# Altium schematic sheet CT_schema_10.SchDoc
size 209 x 185 mm
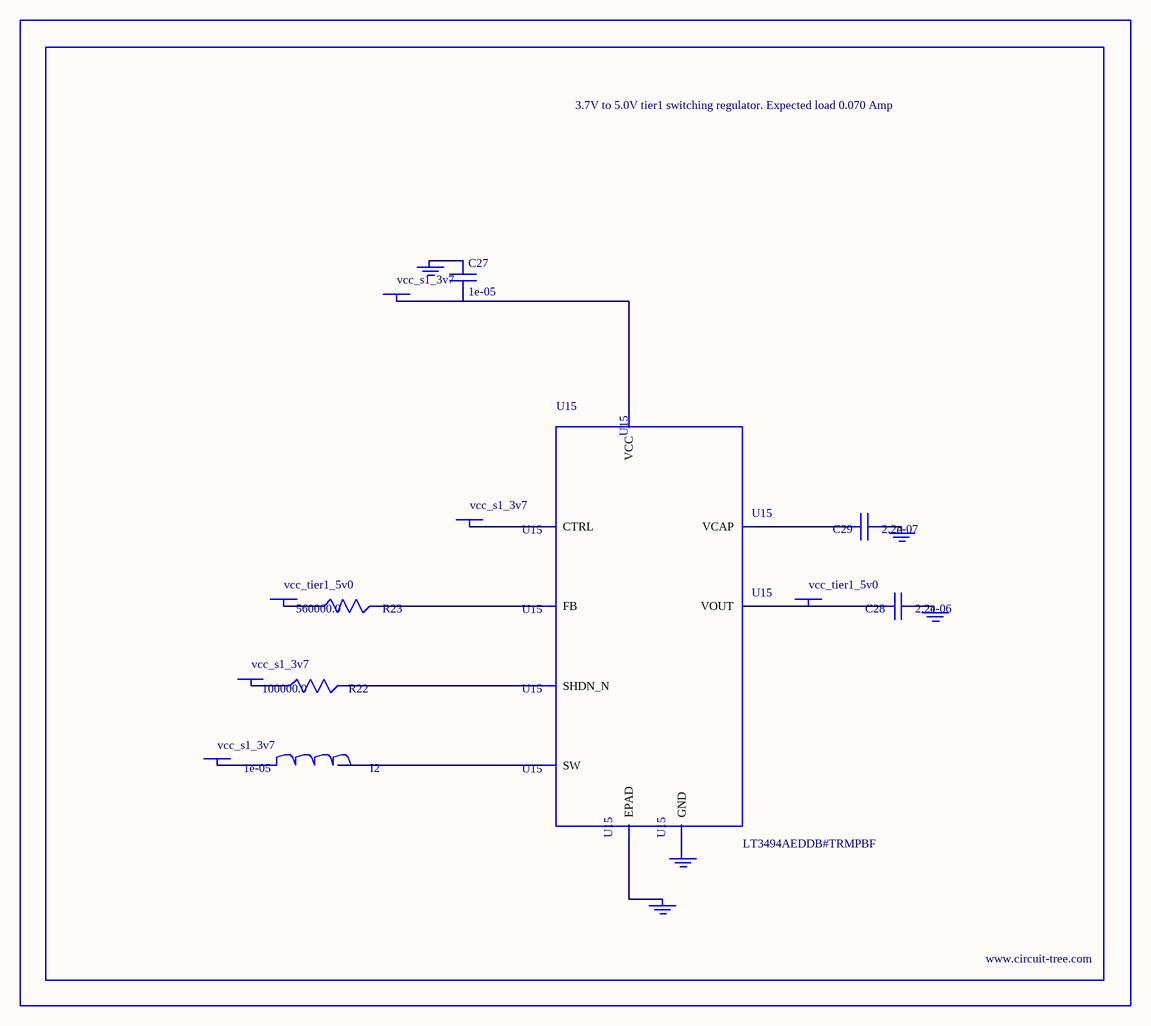
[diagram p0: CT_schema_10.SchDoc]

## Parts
BORDER9  (no value)
C27  1e-05  [C1210]
C28  2.2e-06  [C0603]
C29  2.2e-07  [C0603]
GND_INSTANCE_9_0  (no value)
GND_INSTANCE_9_1  (no value)
GND_INSTANCE_9_2  (no value)
GND_INSTANCE_9_3  (no value)
GND_INSTANCE_9_4  (no value)
I2  1e-05  [L1210]
POWER_INSTANCE_9_0  vcc_s1_3v7
POWER_INSTANCE_9_1  vcc_s1_3v7
POWER_INSTANCE_9_2  vcc_s1_3v7
POWER_INSTANCE_9_3  vcc_s1_3v7
POWER_INSTANCE_9_4  vcc_tier1_5v0
POWER_INSTANCE_9_5  vcc_tier1_5v0
R22  100000.0  [R0603]
R23  560000.0  [R0603]
U15  LT3494AEDDB#TRMPBF  [DFN-8_DDB]

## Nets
NetC27_1: C27.1 GND_INSTANCE_9_0.0(GND)
NetC27_2: C27.2 POWER_INSTANCE_9_1.0(PWR) U15.3(VCC)
NetC28_1: C28.1 GND_INSTANCE_9_1.0(GND)
NetC28_2: C28.2 POWER_INSTANCE_9_5.0(PWR) U15.7(VOUT)
NetC29_1: C29.1 GND_INSTANCE_9_2.0(GND)
NetC29_2: C29.2 U15.8(VCAP)
NetGND_INSTANCE_9_3_0: GND_INSTANCE_9_3.0(GND) U15.9(EPAD)
NetGND_INSTANCE_9_4_0: GND_INSTANCE_9_4.0(GND) U15.2(GND)
NetI2_1: I2.1 POWER_INSTANCE_9_0.0(PWR)
NetI2_2: I2.2 U15.1(SW)
NetPOWER_INSTANCE_9_2_0: POWER_INSTANCE_9_2.0(PWR) U15.4(CTRL)
NetPOWER_INSTANCE_9_3_0: POWER_INSTANCE_9_3.0(PWR) R22.1
NetPOWER_INSTANCE_9_4_0: POWER_INSTANCE_9_4.0(PWR) R23.1
NetR22_2: R22.2 U15.5(SHDN_N)
NetR23_2: R23.2 U15.6(FB)

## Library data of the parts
BORDER9 = BORDER_PAGE9
C27 = C1210C106K5PACTU
C28 = GRM188R61H225KE1115D
C29 = C0603C224K3RAC
GND_INSTANCE_9_0-GND_INSTANCE_9_4 = GND
I2 = CBC3225T100MR
POWER_INSTANCE_9_0-POWER_INSTANCE_9_5 = PWR
R22 = RC0603JR-07100KL
R23 = RC0603JR-07560KL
